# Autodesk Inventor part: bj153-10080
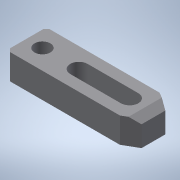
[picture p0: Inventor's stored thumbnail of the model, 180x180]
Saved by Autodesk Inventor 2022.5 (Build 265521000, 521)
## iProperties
Created: 2016-12
Part Number: bj153-10080
Material: 一般
Document SubType Name: Modeling
Designer: imaocorp
Density: 1 g/cm^3
Appearance: 既定
Author: imaocorp
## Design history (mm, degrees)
node "bj153-10080.x_t1"
node "bj153-10080"
node "Base1"
